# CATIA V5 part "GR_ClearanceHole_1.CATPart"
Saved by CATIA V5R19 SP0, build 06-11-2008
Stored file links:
  C:\Program Files\Dassault Systemes\Power Feature\SampleData\GeneralData\GeometricalRules\GeomRuleParts\GR_ClearanceHole_1.CATPart
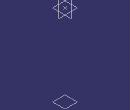
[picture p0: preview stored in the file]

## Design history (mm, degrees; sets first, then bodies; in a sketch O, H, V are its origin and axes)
Set1
  Point1: (0, 0, 0)
  Plane1: type Offset, RefPlane xy-plane
Body1 (main body)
